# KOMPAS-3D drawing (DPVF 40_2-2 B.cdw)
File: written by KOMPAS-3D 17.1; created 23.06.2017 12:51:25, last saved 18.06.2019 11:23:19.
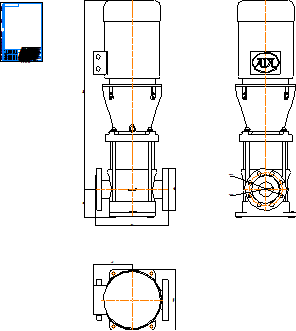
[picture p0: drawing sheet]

Sheet 1: A4, portrait

Title block, sheet 1: name: DPVF 40_2-2 B; material: Внимание! Данный продукт является объектом авторского права ООО «Торговый Дом АДЛ». / Запрещается изменение, копирование, распространение / (в том числе путем копирования на другие сайты и ресурсы в Интернете) / или любое иное использование информации и объектов без предварительного / согласия правообладателя (ООО «Торговый Дом АДЛ»).; scale: 1:1; sheets: 1; organisation: ООО "Торговый дом АДЛ"; sheet format: A4; stored path: C:\Клочков АВ\Насосы\DP PAMS\DPVF 40\Компас 2d\DPVF 40_2-2 B.cdw

Views: Спереди 1
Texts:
  Клочков АВ
  ООО АДЛ ГРУПП
Dimensions and other numbers on the sheet: 365; 197; 306; 209,6; 947,5; 140; 168,1; 76,2; 1:1; 1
